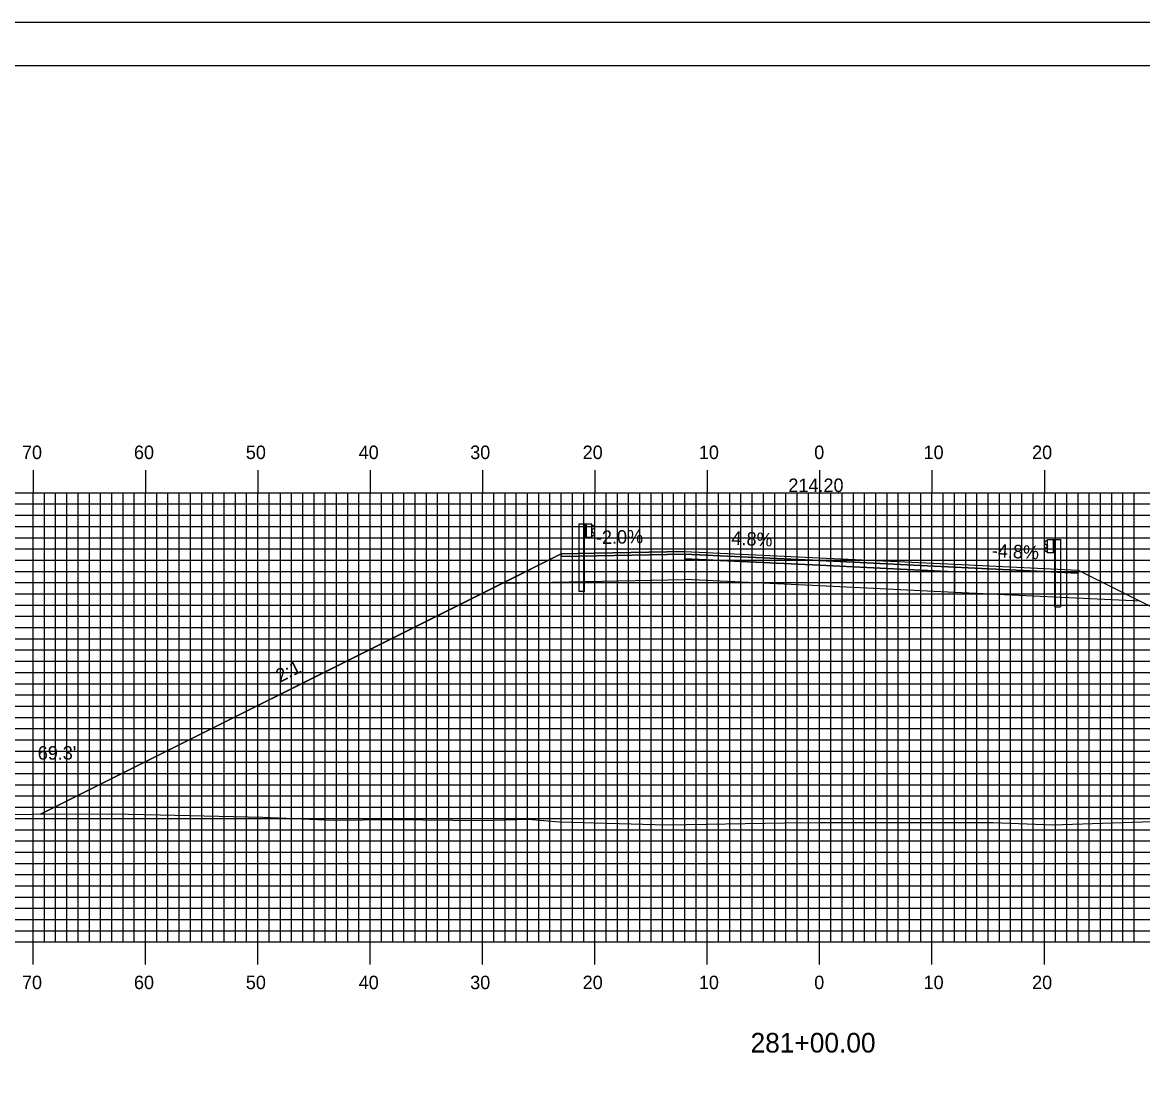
# Model space of a CAD drawing. Extents: x 1810980 to 1811323, y 442591 to 442811.
# Drawn here: x 1811074.9 to 1811174.6, y 442716.9 to 442810.5 of the extents above; entities that cross this region are included whole.
import ezdxf

# ---------------------------------------------------------------- set-up
doc = ezdxf.new("R2010")
doc.units = 0
for name, color, linetype in [('ANNOTATION', 7, 'Continuous'), ('BORDER', 7, 'Continuous'), ('D_Guardrail_Beam_Lt', 7, 'Continuous'), ('D_Guardrail_Beam_Rt', 7, 'Continuous'), ('D_Roadway_Centerline', 7, 'Continuous'), ('D_Roadway_Centerline_Text', 7, 'Continuous'), ('D_Roadway_Edge_Shoulder', 7, 'Continuous'), ('D_Roadway_Edge_TW', 7, 'Continuous'), ('D_Roadway_Pavement', 7, 'Continuous'), ('D_Roadway_SlopeLines', 7, 'Continuous'), ('D_Roadway_SubGrade', 7, 'Continuous'), ('D_Text_Standard', 7, 'Continuous'), ('H_V ANNOTATION', 7, 'Continuous'), ('MAJOR', 7, 'Continuous'), ('MINOR', 7, 'Continuous'), ('PLOT BOUNDARY', 7, 'Continuous'), ('S_Roadway_Centerline', 7, 'Continuous')]:
    doc.layers.add(name, color=color, linetype=linetype)

msp = doc.modelspace()

# ---------------------------------------------------------------- linework, layer by layer
at = {"layer": 'BORDER'}
msp.add_lwpolyline([(1810996.29, 442596.665), (1811316.29, 442596.665), (1811316.29, 442806.665), (1810996.29, 442806.665)], close=True, dxfattribs=at)
at = {"layer": 'D_Guardrail_Beam_Lt'}
for p, q in [((1811124.461, 442765.869), (1811124.461, 442759.869)), ((1811124.931, 442765.869), (1811124.461, 442765.869)), ((1811125.619, 442765.869), (1811124.931, 442765.869)), ((1811124.931, 442765.869), (1811124.931, 442764.703)), ((1811124.994, 442765.869), (1811124.994, 442764.703)), ((1811125.098, 442765.869), (1811125.098, 442764.703)), ((1811125.619, 442764.703), (1811125.619, 442765.869)), ((1811125.619, 442765.786), (1811125.693, 442765.771)), ((1811125.709, 442765.765), (1811125.852, 442765.665)), ((1811124.931, 442764.703), (1811125.619, 442764.703)), ((1811124.952, 442759.869), (1811124.952, 442764.703)), ((1811125.693, 442764.801), (1811125.619, 442764.786)), ((1811125.623, 442765.321), (1811125.623, 442765.251)), ((1811125.852, 442765.522), (1811125.657, 442765.385)), ((1811125.657, 442765.186), (1811125.852, 442765.05)), ((1811125.852, 442764.907), (1811125.709, 442764.807)), ((1811124.952, 442759.869), (1811124.461, 442759.869))]:
    msp.add_line(p, q, dxfattribs=at)
for centre, major_axis, start_param, end_param in [((1811125.685, 442765.731), (0.0417, 0), 0.959931, 1.376053), ((1811125.802, 442765.593), (0.0877, 0), 5.323254, 7.243116), ((1811125.702, 442765.321), (-0.0789, 0), 5.323254, 6.283185), ((1811125.702, 442765.251), (-0.0789, 0), 6.283185, 7.243116), ((1811125.685, 442764.841), (0.0417, 0), 4.907132, 5.323254), ((1811125.802, 442764.979), (0.0877, 0), 5.323254, 7.243116)]:
    msp.add_ellipse(centre, major_axis=major_axis, ratio=0.995501, start_param=start_param, end_param=end_param, dxfattribs=at)
at = {"layer": 'D_Guardrail_Beam_Rt'}
for p, q in [((1811166.071, 442764.389), (1811165.927, 442764.289)), ((1811165.927, 442764.146), (1811166.122, 442764.009)), ((1811166.122, 442763.81), (1811165.927, 442763.674)), ((1811166.161, 442764.41), (1811166.086, 442764.395)), ((1811166.156, 442763.945), (1811166.156, 442763.875)), ((1811166.161, 442764.493), (1811166.848, 442764.493)), ((1811166.161, 442763.327), (1811166.161, 442764.493)), ((1811166.681, 442764.493), (1811166.681, 442763.327)), ((1811166.786, 442764.493), (1811166.786, 442763.327)), ((1811166.848, 442764.493), (1811167.319, 442764.493)), ((1811166.848, 442764.493), (1811166.848, 442763.327)), ((1811167.319, 442764.493), (1811167.319, 442758.493)), ((1811165.927, 442763.531), (1811166.071, 442763.431)), ((1811166.086, 442763.425), (1811166.161, 442763.41)), ((1811166.848, 442763.327), (1811166.161, 442763.327)), ((1811166.827, 442758.493), (1811166.827, 442763.327)), ((1811166.827, 442758.493), (1811167.319, 442758.493))]:
    msp.add_line(p, q, dxfattribs=at)
for centre, major_axis, start_param, end_param in [((1811165.977, 442764.217), (-0.0877, 0), 5.323254, 7.243116), ((1811165.977, 442763.603), (-0.0877, 0), 5.323254, 7.243116), ((1811166.094, 442764.355), (-0.0417, 0), 4.907132, 5.323254), ((1811166.077, 442763.945), (0.0789, 0), 0, 0.959931), ((1811166.077, 442763.875), (0.0789, 0), 5.323254, 6.283185), ((1811166.094, 442763.465), (-0.0417, 0), 0.959931, 1.376053)]:
    msp.add_ellipse(centre, major_axis=major_axis, ratio=0.995501, start_param=start_param, end_param=end_param, dxfattribs=at)
at = {"layer": 'D_Roadway_Centerline'}
msp.add_lwpolyline([(1811076.549, 442740.056), (1811117.681, 442760.622), (1811122.89, 442763.226), (1811125.89, 442763.286), (1811133.89, 442763.446), (1811145.89, 442762.87), (1811157.89, 442762.294), (1811165.89, 442761.91), (1811168.89, 442761.766), (1811174.421, 442759), (1811214.482, 442738.97)], dxfattribs=at)
at = {"layer": 'D_Roadway_Edge_Shoulder'}
for points in [[(1811133.89, 442763.446), (1811125.89, 442763.286), (1811125.89, 442763.286), (1811122.89, 442763.226), (1811122.89, 442762.976), (1811133.89, 442763.196)], [(1811157.89, 442762.294), (1811165.89, 442761.91), (1811165.89, 442761.91), (1811168.89, 442761.766), (1811168.89, 442761.516), (1811157.89, 442762.044)]]:
    msp.add_lwpolyline(points, close=True, dxfattribs=at)
at = {"layer": 'D_Roadway_Edge_TW'}
msp.add_lwpolyline([(1811133.89, 442763.196), (1811133.89, 442763.446), (1811145.89, 442762.87), (1811157.89, 442762.294), (1811157.89, 442762.044), (1811145.89, 442762.62)], close=True, dxfattribs=at)
at = {"layer": 'D_Roadway_Pavement'}
msp.add_lwpolyline([(1811133.89, 442762.779), (1811133.89, 442763.196), (1811145.89, 442762.62), (1811157.89, 442762.044), (1811157.89, 442761.627), (1811145.89, 442762.203)], close=True, dxfattribs=at)
for points in [[(1811133.89, 442763.196), (1811133.89, 442762.779)], [(1811157.89, 442762.044), (1811157.89, 442761.627)]]:
    msp.add_lwpolyline(points, dxfattribs=at)
at = {"layer": 'D_Roadway_SlopeLines'}
for points in [[(1811122.89, 442763.226), (1811076.549, 442740.056)], [(1811168.89, 442761.766), (1811214.482, 442738.97)]]:
    msp.add_lwpolyline(points, dxfattribs=at)
at = {"layer": 'D_Roadway_SubGrade'}
for points in [[(1811133.89, 442762.779), (1811133.89, 442763.196), (1811122.89, 442762.976), (1811122.89, 442763.226), (1811117.681, 442760.622), (1811133.89, 442760.946)], [(1811133.89, 442760.946), (1811133.89, 442763.196), (1811133.89, 442762.779), (1811145.89, 442762.203), (1811157.89, 442761.627), (1811157.89, 442762.044), (1811157.89, 442759.794), (1811145.89, 442760.37)], [(1811157.89, 442761.627), (1811157.89, 442762.044), (1811168.89, 442761.516), (1811168.89, 442761.766), (1811174.421, 442759), (1811157.89, 442759.794)]]:
    msp.add_lwpolyline(points, close=True, dxfattribs=at)
at = {"layer": 'MAJOR'}
for p, q in [((1811075.89, 442770.669), (1811075.89, 442768.665)), ((1811085.89, 442770.669), (1811085.89, 442768.665)), ((1811095.89, 442770.669), (1811095.89, 442768.665)), ((1811105.89, 442770.669), (1811105.89, 442768.665)), ((1811115.89, 442770.669), (1811115.89, 442768.665)), ((1811125.89, 442770.669), (1811125.89, 442768.665)), ((1811135.89, 442770.669), (1811135.89, 442768.665)), ((1811145.89, 442770.669), (1811145.89, 442768.665)), ((1811155.89, 442770.669), (1811155.89, 442768.665)), ((1811165.89, 442770.669), (1811165.89, 442768.665)), ((1811005.89, 442768.665), (1811285.89, 442768.665)), ((1811005.89, 442768.665), (1811285.89, 442768.665)), ((1811075.89, 442728.665), (1811075.89, 442768.665)), ((1811085.89, 442728.665), (1811085.89, 442768.665)), ((1811095.89, 442728.665), (1811095.89, 442768.665)), ((1811105.89, 442728.665), (1811105.89, 442768.665)), ((1811115.89, 442728.665), (1811115.89, 442768.665)), ((1811125.89, 442728.665), (1811125.89, 442768.665)), ((1811135.89, 442728.665), (1811135.89, 442768.665)), ((1811145.89, 442728.665), (1811145.89, 442768.665)), ((1811155.89, 442728.665), (1811155.89, 442768.665)), ((1811165.89, 442728.665), (1811165.89, 442768.665)), ((1811005.89, 442763.665), (1811285.89, 442763.665)), ((1811005.89, 442758.665), (1811285.89, 442758.665)), ((1811005.89, 442753.665), (1811285.89, 442753.665)), ((1811005.89, 442748.665), (1811285.89, 442748.665)), ((1811005.89, 442743.665), (1811285.89, 442743.665)), ((1811005.89, 442738.665), (1811285.89, 442738.665)), ((1811005.89, 442733.665), (1811285.89, 442733.665)), ((1811005.89, 442728.665), (1811285.89, 442728.665)), ((1811005.89, 442728.665), (1811285.89, 442728.665)), ((1811075.89, 442726.661), (1811075.89, 442728.665)), ((1811085.89, 442726.661), (1811085.89, 442728.665)), ((1811095.89, 442726.661), (1811095.89, 442728.665)), ((1811105.89, 442726.661), (1811105.89, 442728.665)), ((1811115.89, 442726.661), (1811115.89, 442728.665)), ((1811125.89, 442726.661), (1811125.89, 442728.665)), ((1811135.89, 442726.661), (1811135.89, 442728.665)), ((1811145.89, 442726.661), (1811145.89, 442728.665)), ((1811155.89, 442726.661), (1811155.89, 442728.665)), ((1811165.89, 442726.661), (1811165.89, 442728.665))]:
    msp.add_line(p, q, dxfattribs=at)
at = {"layer": 'MINOR'}
for p, q in [((1811076.89, 442728.665), (1811076.89, 442768.665)), ((1811077.89, 442728.665), (1811077.89, 442768.665)), ((1811078.89, 442728.665), (1811078.89, 442768.665)), ((1811079.89, 442728.665), (1811079.89, 442768.665)), ((1811080.89, 442728.665), (1811080.89, 442768.665)), ((1811081.89, 442728.665), (1811081.89, 442768.665)), ((1811082.89, 442728.665), (1811082.89, 442768.665)), ((1811083.89, 442728.665), (1811083.89, 442768.665)), ((1811084.89, 442728.665), (1811084.89, 442768.665)), ((1811086.89, 442728.665), (1811086.89, 442768.665)), ((1811087.89, 442728.665), (1811087.89, 442768.665)), ((1811088.89, 442728.665), (1811088.89, 442768.665)), ((1811089.89, 442728.665), (1811089.89, 442768.665)), ((1811090.89, 442728.665), (1811090.89, 442768.665)), ((1811091.89, 442728.665), (1811091.89, 442768.665)), ((1811092.89, 442728.665), (1811092.89, 442768.665)), ((1811093.89, 442728.665), (1811093.89, 442768.665)), ((1811094.89, 442728.665), (1811094.89, 442768.665)), ((1811096.89, 442728.665), (1811096.89, 442768.665)), ((1811097.89, 442728.665), (1811097.89, 442768.665)), ((1811098.89, 442728.665), (1811098.89, 442768.665)), ((1811099.89, 442728.665), (1811099.89, 442768.665)), ((1811100.89, 442728.665), (1811100.89, 442768.665)), ((1811101.89, 442728.665), (1811101.89, 442768.665)), ((1811102.89, 442728.665), (1811102.89, 442768.665)), ((1811103.89, 442728.665), (1811103.89, 442768.665)), ((1811104.89, 442728.665), (1811104.89, 442768.665)), ((1811106.89, 442728.665), (1811106.89, 442768.665)), ((1811107.89, 442728.665), (1811107.89, 442768.665)), ((1811108.89, 442728.665), (1811108.89, 442768.665)), ((1811109.89, 442728.665), (1811109.89, 442768.665)), ((1811110.89, 442728.665), (1811110.89, 442768.665)), ((1811111.89, 442728.665), (1811111.89, 442768.665)), ((1811112.89, 442728.665), (1811112.89, 442768.665)), ((1811113.89, 442728.665), (1811113.89, 442768.665)), ((1811114.89, 442728.665), (1811114.89, 442768.665)), ((1811116.89, 442728.665), (1811116.89, 442768.665)), ((1811117.89, 442728.665), (1811117.89, 442768.665)), ((1811118.89, 442728.665), (1811118.89, 442768.665)), ((1811119.89, 442728.665), (1811119.89, 442768.665)), ((1811120.89, 442728.665), (1811120.89, 442768.665)), ((1811121.89, 442728.665), (1811121.89, 442768.665)), ((1811122.89, 442728.665), (1811122.89, 442768.665)), ((1811123.89, 442728.665), (1811123.89, 442768.665)), ((1811124.89, 442728.665), (1811124.89, 442768.665)), ((1811126.89, 442728.665), (1811126.89, 442768.665)), ((1811127.89, 442728.665), (1811127.89, 442768.665)), ((1811128.89, 442728.665), (1811128.89, 442768.665)), ((1811129.89, 442728.665), (1811129.89, 442768.665)), ((1811130.89, 442728.665), (1811130.89, 442768.665)), ((1811131.89, 442728.665), (1811131.89, 442768.665)), ((1811132.89, 442728.665), (1811132.89, 442768.665)), ((1811133.89, 442728.665), (1811133.89, 442768.665)), ((1811134.89, 442728.665), (1811134.89, 442768.665)), ((1811136.89, 442728.665), (1811136.89, 442768.665)), ((1811137.89, 442728.665), (1811137.89, 442768.665)), ((1811138.89, 442728.665), (1811138.89, 442768.665)), ((1811139.89, 442728.665), (1811139.89, 442768.665)), ((1811140.89, 442728.665), (1811140.89, 442768.665)), ((1811141.89, 442728.665), (1811141.89, 442768.665)), ((1811142.89, 442728.665), (1811142.89, 442768.665)), ((1811143.89, 442728.665), (1811143.89, 442768.665)), ((1811144.89, 442728.665), (1811144.89, 442768.665)), ((1811146.89, 442728.665), (1811146.89, 442768.665)), ((1811147.89, 442728.665), (1811147.89, 442768.665)), ((1811148.89, 442728.665), (1811148.89, 442768.665)), ((1811149.89, 442728.665), (1811149.89, 442768.665)), ((1811150.89, 442728.665), (1811150.89, 442768.665)), ((1811151.89, 442728.665), (1811151.89, 442768.665)), ((1811152.89, 442728.665), (1811152.89, 442768.665)), ((1811153.89, 442728.665), (1811153.89, 442768.665)), ((1811154.89, 442728.665), (1811154.89, 442768.665)), ((1811156.89, 442728.665), (1811156.89, 442768.665)), ((1811157.89, 442728.665), (1811157.89, 442768.665)), ((1811158.89, 442728.665), (1811158.89, 442768.665)), ((1811159.89, 442728.665), (1811159.89, 442768.665)), ((1811160.89, 442728.665), (1811160.89, 442768.665)), ((1811161.89, 442728.665), (1811161.89, 442768.665)), ((1811162.89, 442728.665), (1811162.89, 442768.665)), ((1811163.89, 442728.665), (1811163.89, 442768.665)), ((1811164.89, 442728.665), (1811164.89, 442768.665)), ((1811166.89, 442728.665), (1811166.89, 442768.665)), ((1811167.89, 442728.665), (1811167.89, 442768.665)), ((1811168.89, 442728.665), (1811168.89, 442768.665)), ((1811169.89, 442728.665), (1811169.89, 442768.665)), ((1811170.89, 442728.665), (1811170.89, 442768.665)), ((1811171.89, 442728.665), (1811171.89, 442768.665)), ((1811172.89, 442728.665), (1811172.89, 442768.665)), ((1811173.89, 442728.665), (1811173.89, 442768.665)), ((1811005.89, 442767.665), (1811285.89, 442767.665)), ((1811005.89, 442766.665), (1811285.89, 442766.665)), ((1811005.89, 442765.665), (1811285.89, 442765.665)), ((1811005.89, 442764.665), (1811285.89, 442764.665)), ((1811005.89, 442762.665), (1811285.89, 442762.665)), ((1811005.89, 442761.665), (1811285.89, 442761.665)), ((1811005.89, 442760.665), (1811285.89, 442760.665)), ((1811005.89, 442759.665), (1811285.89, 442759.665)), ((1811005.89, 442757.665), (1811285.89, 442757.665)), ((1811005.89, 442756.665), (1811285.89, 442756.665)), ((1811005.89, 442755.665), (1811285.89, 442755.665)), ((1811005.89, 442754.665), (1811285.89, 442754.665)), ((1811005.89, 442752.665), (1811285.89, 442752.665)), ((1811005.89, 442751.665), (1811285.89, 442751.665)), ((1811005.89, 442750.665), (1811285.89, 442750.665)), ((1811005.89, 442749.665), (1811285.89, 442749.665)), ((1811005.89, 442747.665), (1811285.89, 442747.665)), ((1811005.89, 442746.665), (1811285.89, 442746.665)), ((1811005.89, 442745.665), (1811285.89, 442745.665)), ((1811005.89, 442744.665), (1811285.89, 442744.665)), ((1811005.89, 442742.665), (1811285.89, 442742.665)), ((1811005.89, 442741.665), (1811285.89, 442741.665)), ((1811005.89, 442740.665), (1811285.89, 442740.665)), ((1811005.89, 442739.665), (1811285.89, 442739.665)), ((1811005.89, 442737.665), (1811285.89, 442737.665)), ((1811005.89, 442736.665), (1811285.89, 442736.665)), ((1811005.89, 442735.665), (1811285.89, 442735.665)), ((1811005.89, 442734.665), (1811285.89, 442734.665)), ((1811005.89, 442732.665), (1811285.89, 442732.665)), ((1811005.89, 442731.665), (1811285.89, 442731.665)), ((1811005.89, 442730.665), (1811285.89, 442730.665)), ((1811005.89, 442729.665), (1811285.89, 442729.665))]:
    msp.add_line(p, q, dxfattribs=at)
at = {"layer": 'PLOT BOUNDARY'}
msp.add_lwpolyline([(1810980.103, 442590.547), (1811320.103, 442590.547), (1811320.103, 442810.547), (1810980.103, 442810.547)], close=True, dxfattribs=at)
at = {"layer": 'S_Roadway_Centerline'}
msp.add_lwpolyline([(1811005.89, 442740.981), (1811014.13, 442740.752), (1811025.02, 442740.778), (1811027.304, 442740.754), (1811043.548, 442740.488), (1811048.646, 442740.324), (1811057.756, 442740.137), (1811064.376, 442740.008), (1811075.77, 442740.052), (1811082.957, 442740.087), (1811087.197, 442739.982), (1811096.319, 442739.788), (1811102.579, 442739.515), (1811107.932, 442739.559), (1811115.909, 442739.48), (1811119.943, 442739.613), (1811122.739, 442739.366), (1811132.296, 442739.098), (1811142.777, 442739.287), (1811145.974, 442739.298), (1811161.345, 442739.301), (1811166.62, 442739.104), (1811176.407, 442739.435)], dxfattribs=at)

# ---------------------------------------------------------------- texts
at = {"layer": 'ANNOTATION'}
for s, rotation, p in [('-2.0%', 1.14576, (1811125.996, 442764.089)), ('4.8%', 357.25191, (1811138.019, 442764.05)), ('-4.8%', 357.25191, (1811161.198, 442762.937)), ('2:1', 26.56505, (1811097.864, 442751.749))]:
    msp.add_text(s, height=1.2, rotation=rotation, dxfattribs=at).set_placement(p)
at = {"layer": 'D_Roadway_Centerline'}
for s, p in [('C', (1811145.884, 442762.87)), ('L', (1811145.89, 442762.863))]:
    msp.add_text(s, height=0.0146, dxfattribs=at).set_placement(p)
at = {"layer": 'D_Roadway_Centerline_Text'}
msp.add_text('214.20', height=1.2, dxfattribs=at).set_placement((1811143.107, 442768.731))
at = {"layer": 'D_Text_Standard'}
msp.add_text("69.3'", height=1.2, dxfattribs=at).set_placement((1811076.296, 442744.903))
at = {"layer": 'H_V ANNOTATION'}
for s, height, p in [('70', 1.2, (1811074.894, 442771.665)), ('60', 1.2, (1811084.862, 442771.665)), ('50', 1.2, (1811094.819, 442771.665)), ('40', 1.2, (1811104.862, 442771.665)), ('30', 1.2, (1811114.787, 442771.665)), ('20', 1.2, (1811124.798, 442771.665)), ('10', 1.2, (1811135.14, 442771.665)), ('0', 1.2, (1811145.408, 442771.665)), ('10', 1.2, (1811155.14, 442771.665)), ('20', 1.2, (1811164.798, 442771.665)), ('70', 1.2, (1811074.894, 442724.465)), ('60', 1.2, (1811084.862, 442724.465)), ('50', 1.2, (1811094.819, 442724.465)), ('40', 1.2, (1811104.862, 442724.465)), ('30', 1.2, (1811114.787, 442724.465)), ('20', 1.2, (1811124.798, 442724.465)), ('10', 1.2, (1811135.14, 442724.465)), ('0', 1.2, (1811145.408, 442724.465)), ('10', 1.2, (1811155.14, 442724.465)), ('20', 1.2, (1811164.798, 442724.465)), ('281+00.00', 1.75, (1811139.741, 442718.821))]:
    msp.add_text(s, height=height, dxfattribs=at).set_placement(p)

doc.saveas('drawing.dxf')
